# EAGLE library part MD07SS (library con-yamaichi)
YAMAICHI CONNECTOR
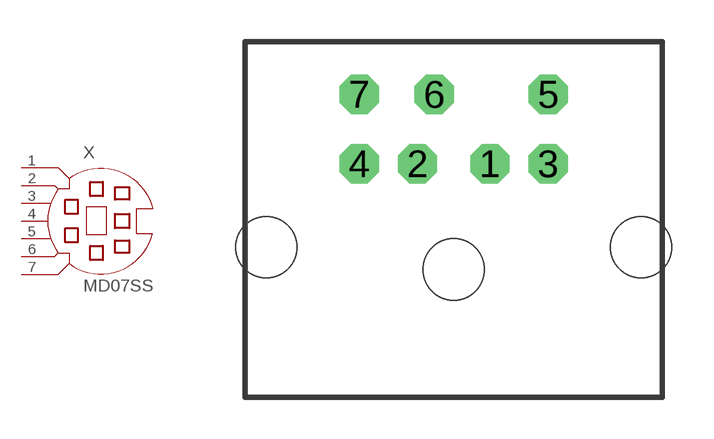
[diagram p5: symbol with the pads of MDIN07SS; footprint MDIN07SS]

Designator prefix X

## MD07SS (OC_FARNELL: unknown; OC_NEWARK: unknown)  [MDIN07SS]
1  1  pas
2  2  pas
3  3  pas
4  4  pas
5  5  pas
6  6  pas
7  7  pas

## Footprint MDIN07SS (pad centres in mm)
Mini Din YAMAICHI CONNECTOR
drill 0.9 octagon: 1 1.3,8.5; 2 -1.3,8.5; 3 3.4,8.5; 4 -3.4,8.5; 5 3.4,11; 6 -0.7,11; 7 -3.4,11
hole 2.2 at -6.75,5.5
hole 2.2 at 0,4.7
hole 2.2 at 6.75,5.5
